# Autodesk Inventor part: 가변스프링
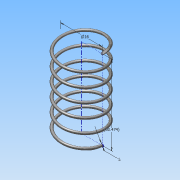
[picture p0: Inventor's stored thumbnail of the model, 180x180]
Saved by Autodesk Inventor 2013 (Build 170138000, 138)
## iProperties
Created: 2016-12
Part Number: 가변스프링
Material: 스테인리스강
Document SubType Name: Modeling
Designer: Administrator
Density: 8.08 g/cm^3
Mass: 1.90059 g
Surface Area: 9.47237 cm^2
Volume: 0.235222 cm^3
Author: Administrator
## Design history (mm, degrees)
sketch "스케치1"
  geometry: L1 (0, 0)-(8, 0); L2 (8, 0)-(8, 30.474); L3 (8, 30.474)-(0, 30.474); L4 (0, 30.474)-(0, 0); C1 r 0.5 at (8, 0)
  constraints: 8 end point, 2 parallel, 1 centre point, 1 coincident, 1 horizontal, 1 perpendicular
  dimensions: "d0" = 1 diameter of C1; "d1" = 30.4737 distance of L1.end L2.end (derived); "d2" = 16 diameter of L2 L4
feature "코일1" pitch "d3" = 10; turns "d5" = 6; dims "d4" = 30.4737 (= d1), "d6" = 0, angle "d7" = 90 deg, angle "d8" = 90 deg, "d9" = 0, "d10" = 0
sketch "스케치2"
  geometry: L1 (-7.5, 0)-(-8.5, 0) reference; 1 further point
  constraints: 1 horizontal alignment
extrude "돌출1" cut sketch "스케치2" stored distance "d11" = 10; taper "d12" = 0 deg
node "작업 평면1"
sketch "스케치3"
  geometry: L1 (-0.5, 0)-(0.5, 0) reference; 1 further point
  constraints: 1 horizontal alignment
extrude "돌출2" cut sketch "스케치3" stored distance "d14" = 10; taper "d15" = 0 deg
node "솔리드1"
node "절단 모서리 투영1"
node "절단 모서리 투영2"
other parameters: "d13" = 90 deg
